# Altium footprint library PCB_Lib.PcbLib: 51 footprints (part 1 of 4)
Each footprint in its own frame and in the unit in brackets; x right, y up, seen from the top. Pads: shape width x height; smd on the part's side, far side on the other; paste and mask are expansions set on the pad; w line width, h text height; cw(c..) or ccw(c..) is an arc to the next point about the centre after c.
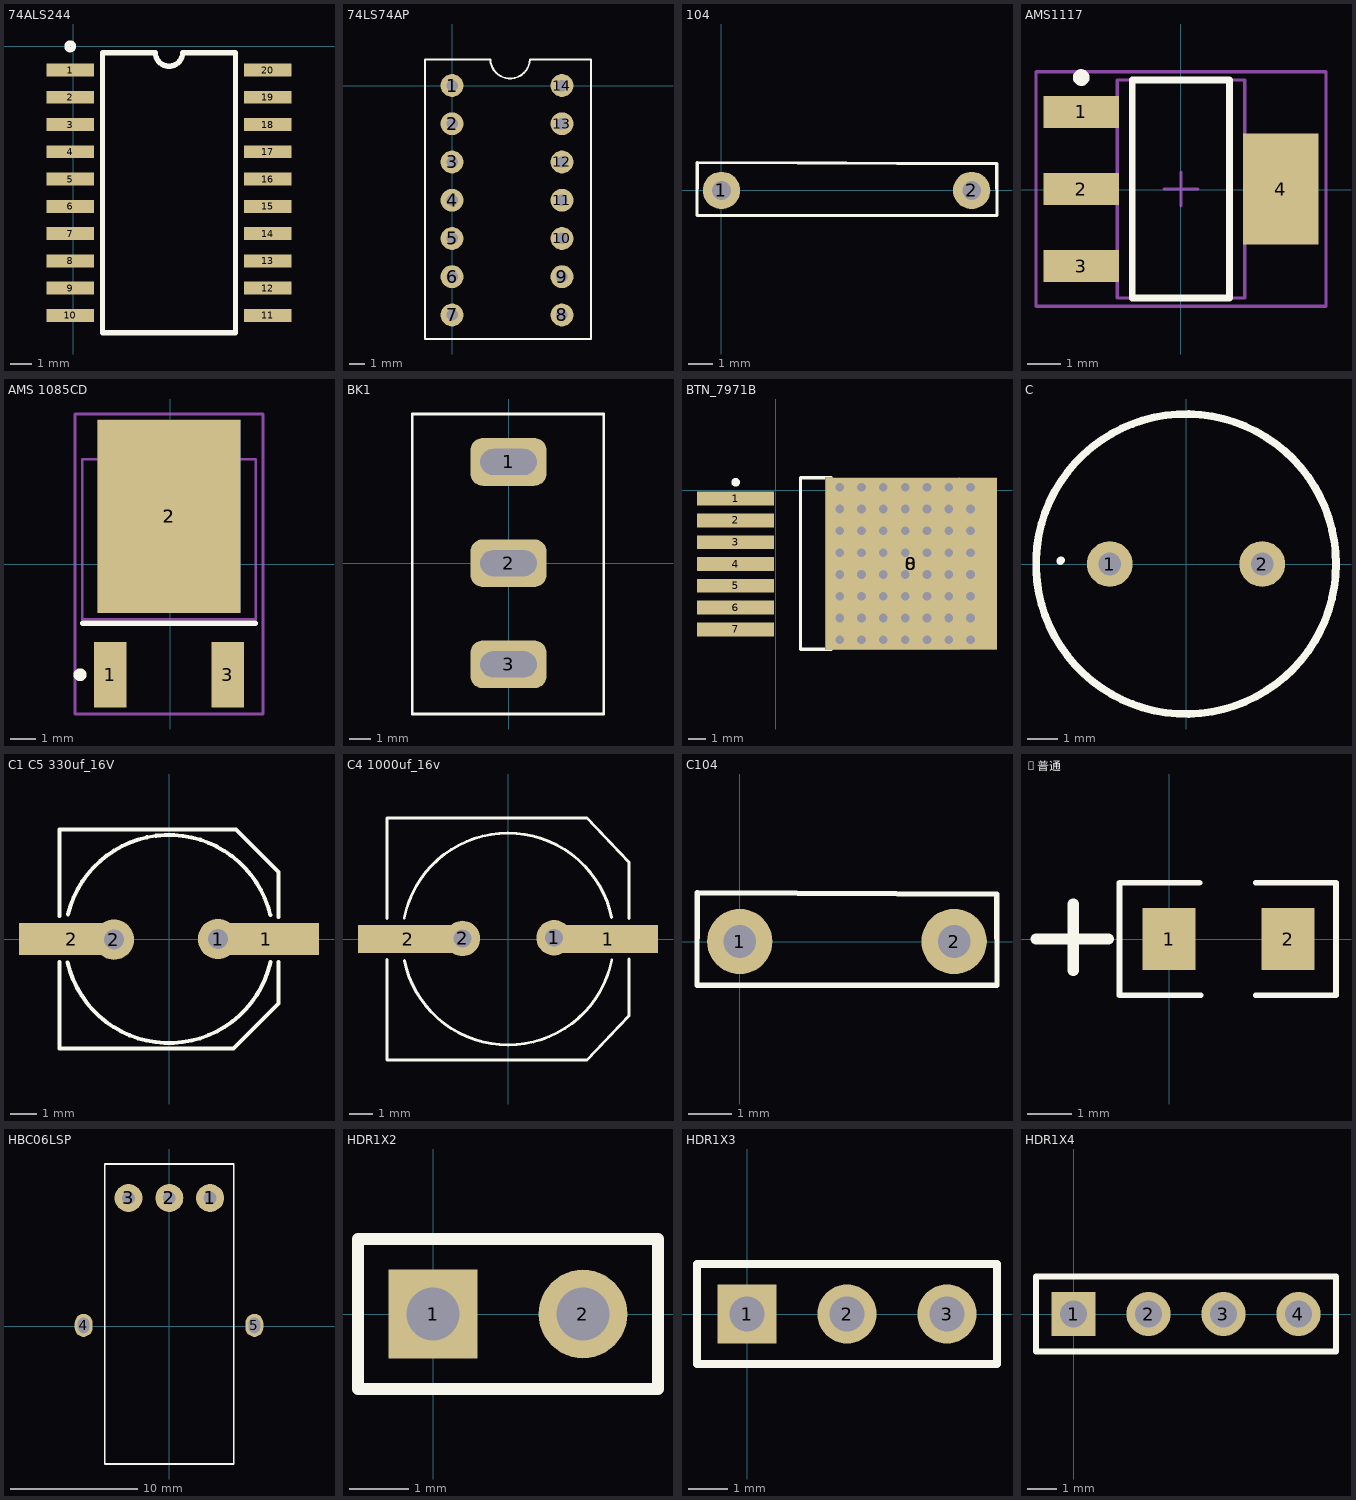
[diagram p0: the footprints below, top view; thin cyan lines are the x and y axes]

## 74ALS244 [mm]
pads (20):
  rect 2.2x0.6 smd: 1(-0.15,-1.1) 2(-0.15,-2.37) 3(-0.15,-3.64) 4(-0.15,-4.91) 5(-0.15,-6.18) 6(-0.15,-7.45) 7(-0.15,-8.72) 8(-0.15,-9.99) 9(-0.15,-11.26) 10(-0.15,-12.53) 11(9.05,-12.53) 12(9.05,-11.26) 13(9.05,-9.99) 14(9.05,-8.72) 15(9.05,-7.45) 16(9.05,-6.18) 17(9.05,-4.91) 18(9.05,-3.64) 19(9.05,-2.37) 20(9.05,-1.1)
Top Overlay:
  circle w0.25: c-0.15,0 r0.15
  lines w0.25: 1.35,-13.34 1.35,-0.29 3.815,-0.29 ccw(c4.45,-0.29) 5.085,-0.29 7.55,-0.29 7.55,-13.34 1.35,-13.34

## 74LS74AP [mil]
pads (14):
  round 60 hole 30 square: 1(0,0)
  round 60 hole 30: 2(0,-100) 3(0,-200) 4(0,-300) 5(0,-400) 6(0,-500) 7(0,-600) 8(287.4,-600) 9(287.4,-500) 10(287.4,-400) 11(287.4,-300) 12(287.4,-200) 13(287.4,-100) 14(287.4,0)
Top Overlay:
  lines w5: 100,68 -71,68 -71,-663 235,-663 363.63,-663 363.63,68 203.48,68 ; 100.04,68 ccw(c151.74,70) 203.44,68

## 104 [mil]
pads (2):
  round 60 hole 30: 1(0,0) 2(401.57,0)
Top Overlay:
  lines w5: -39.29,-40 442.2,-40 441.85,42.84 -38.91,44.65 -39.29,-40

## AMS1117 [mm]
height 1.65
pads (4):
  rect 2.25x0.95 smd: 1(-2.975,2.325) 2(-2.975,0.025) 3(-2.975,-2.275)
  rect 2.25x3.3 smd: 4(2.975,0.025)
Top Overlay:
  circle w0.25: c-2.975,3.35 r0.125
  lines w0.2: -1.45,-3.225 -1.45,3.275 1.45,3.275 1.45,-3.225 -1.45,-3.225
Mechanical 13:
  lines w0.1: -1.9,-3.225 -1.9,3.275 1.9,3.275 1.9,-3.225 -1.9,-3.225
Mechanical 15:
  lines w0.1: -0.5,0.025 0.5,0.025 ; 0,-0.475 0,0.525 ; -4.325,-3.475 -4.325,3.525 4.325,3.525 4.325,-3.475 -4.325,-3.475
3D body: height 1.65, standoff 0.1, extent -1.9,-3.225 1.9,3.275

## AMS 1085CD [mm]
pads (4):
  rect 1.25x2.55 smd: 1(-2.331,-4.3) 3(2.229,-4.3)
  rect 5.55x7.5 smd: 2(-0.051,1.85)
  rect 5.55x7.5 smd far side: 2(-0.051,1.854)
Top Overlay:
  circle w0.25: c-3.506,-4.3 r0.125
  lines w0.2: -3.401,-2.3 3.299,-2.3
Mechanical 13:
  lines w0.1: -3.426,-2.15 -3.426,4.07 3.324,4.07 3.324,-2.15 -3.426,-2.15
Mechanical 15:
  lines w0.1: -0.551,0 0.449,0 ; -0.051,-0.5 -0.051,0.5 ; -3.701,-5.825 -3.701,5.825 3.599,5.825 3.599,-5.825 -3.701,-5.825
3D body: height 2.38, standoff 0.46, extent -3.426,-2.15 3.324,4.07

## BK1 [mm]
pads (3):
  rrect50% 3.5x2.2 hole 1.2 slot 2.6 at 0 deg: 1(0,4.67) 2(0,0) 3(0,-4.67)
Top Overlay:
  lines w0.127: -4.445,-6.96 -4.445,6.883 4.394,6.883 4.394,5.661 4.394,-6.96 -4.445,-6.96

## BTN_7971B [mm]
height 4.4
pads (9):
  rect 10x10 smd far side: 0(7.896,-4.267)
  rect 4.5x0.8 smd: 1(-2.334,-0.483) 2(-2.334,-1.753) 3(-2.334,-3.023) 4(-2.334,-4.293) 5(-2.334,-5.563) 6(-2.334,-6.833) 7(-2.334,-8.103)
  rect 10x10 smd: 8(7.896,-4.267)
via 8.814,-4.902 diameter 0.762 hole 0.508
via 11.354,-1.092 diameter 0.762 hole 0.508
via 11.354,-2.362 diameter 0.762 hole 0.508
via 11.354,-3.632 diameter 0.762 hole 0.508
via 11.354,-4.902 diameter 0.762 hole 0.508
via 10.084,-1.092 diameter 0.762 hole 0.508
via 10.084,-2.362 diameter 0.762 hole 0.508
via 10.084,-3.632 diameter 0.762 hole 0.508
via 10.084,-4.902 diameter 0.762 hole 0.508
via 8.814,-1.092 diameter 0.762 hole 0.508
via 8.814,-2.362 diameter 0.762 hole 0.508
via 8.814,-3.632 diameter 0.762 hole 0.508
via 7.544,-1.092 diameter 0.762 hole 0.508
via 7.544,-2.362 diameter 0.762 hole 0.508
via 7.544,-3.632 diameter 0.762 hole 0.508
via 7.544,-4.902 diameter 0.762 hole 0.508
via 6.274,-1.092 diameter 0.762 hole 0.508
via 6.274,-2.362 diameter 0.762 hole 0.508
via 6.274,-3.632 diameter 0.762 hole 0.508
via 6.274,-4.902 diameter 0.762 hole 0.508
via 5.004,-1.092 diameter 0.762 hole 0.508
via 5.004,-2.362 diameter 0.762 hole 0.508
via 5.004,-3.632 diameter 0.762 hole 0.508
via 5.004,-4.902 diameter 0.762 hole 0.508
via 11.354,-6.172 diameter 0.762 hole 0.508
via 11.354,-7.442 diameter 0.762 hole 0.508
via 11.354,-8.712 diameter 0.762 hole 0.508
via 10.084,-6.172 diameter 0.762 hole 0.508
via 10.084,-7.442 diameter 0.762 hole 0.508
via 10.084,-8.712 diameter 0.762 hole 0.508
via 8.814,-6.172 diameter 0.762 hole 0.508
via 8.814,-7.442 diameter 0.762 hole 0.508
via 8.814,-8.712 diameter 0.762 hole 0.508
via 7.544,-6.172 diameter 0.762 hole 0.508
via 7.544,-7.442 diameter 0.762 hole 0.508
via 7.544,-8.712 diameter 0.762 hole 0.508
via 6.274,-6.172 diameter 0.762 hole 0.508
via 6.274,-7.442 diameter 0.762 hole 0.508
via 6.274,-8.712 diameter 0.762 hole 0.508
via 5.004,-6.172 diameter 0.762 hole 0.508
via 5.004,-7.442 diameter 0.762 hole 0.508
via 5.004,-8.712 diameter 0.762 hole 0.508
via 11.354,0.178 diameter 0.762 hole 0.508
via 10.084,0.178 diameter 0.762 hole 0.508
via 8.814,0.178 diameter 0.762 hole 0.508
via 7.544,0.178 diameter 0.762 hole 0.508
via 6.274,0.178 diameter 0.762 hole 0.508
via 5.004,0.178 diameter 0.762 hole 0.508
via 3.734,-8.712 diameter 0.762 hole 0.508
via 3.734,-7.442 diameter 0.762 hole 0.508
via 3.734,-4.902 diameter 0.762 hole 0.508
via 3.734,-6.172 diameter 0.762 hole 0.508
via 3.734,-3.632 diameter 0.762 hole 0.508
via 3.734,-2.362 diameter 0.762 hole 0.508
via 3.734,-1.092 diameter 0.762 hole 0.508
via 3.734,0.178 diameter 0.762 hole 0.508
Top Overlay:
  circle w0.25: c-2.334,0.467 r0.125
  lines w0.2: 3.246,-9.267 1.446,-9.267 1.446,0.733 3.246,0.733
Mechanical 13:
  lines w0.1: 1.446,0.733 1.446,-9.267 10.696,-9.267 10.696,0.733
Mechanical 15:
  lines w0.1: 3.596,-4.267 4.596,-4.267 ; 4.096,-4.767 4.096,-3.767
3D body: height 4.4, standoff 0.5, extent 1.446,-9.267 10.696,0.733

## C [mil]
pads (2):
  round 60 hole 30: 1(-100,0) 2(100,0)
Top Overlay:
  circle w10: c0,0 r196.85
  lines w10: -165,4 -164,5

## C1 C5 330uf_16V [mil]
pads (4):
  round 60 hole 30: 1(73,0) 2(-82,-1)
  rect 157.48x47.24 smd: 1(144.69,0) 2(-144.69,0)
Top Overlay:
  lines w6: -163.39,-34 -163.39,-163.39 96,-163.39 163.39,-96 163.39,-34 ; -163.39,34 -163.39,163.39 99.61,163.39 163.39,99.61 163.39,33 ; -151.06,-34.7 ccw(c0,0) 151.12,-34.48 ; -150.55,36.87 cw(c0,0) 150.84,35.67

## C4 1000uf_16v [mil]
pads (4):
  round 60 hole 30: 1(78,2) 2(-77,1)
  rect 169.29x47.24 smd: 1(169.29,0) 2(-169.29,0)
Top Overlay:
  lines w5: -204.72,-35 -204.72,-204.72 133.86,-204.72 204.72,-129.92 204.72,-34 ; -204.72,35 -204.72,204.72 133.86,204.72 204.72,129.92 204.72,35 ; -175.68,35.75 cw(c0,0) 175.52,36.52 ; -175.52,-36.52 ccw(c0,0) 175.68,-35.75

## C104 [mil]
pads (2):
  round 60 hole 30: 1(0,0) 2(196.85,0)
Top Overlay:
  lines w5: -39.29,-40 236.22,-40 235.86,43.62 -38.91,44.65 -39.29,-40

## C普通 [mm]
pads (2):
  rect 1.2x1.4 smd: 1(0,0) 2(2.68,0)
Top Overlay:
  lines w0.127: 0.686,1.27 -1.118,1.27 -1.118,-1.27 0.711,-1.27 ; 1.956,-1.27 3.734,-1.27 3.759,-1.27 3.759,1.27 1.956,1.27
  lines w0.254: -2.997,0 -1.372,0 ; -2.159,-0.711 -2.159,0.787 -2.159,0

## HBC06LSP [mm]
pads (5):
  round 2.2 hole 1 square: 1(3.226,10.084)
  round 2.2 hole 1: 2(0.026,10.084) 3(-3.174,10.084)
  oval 1.4x1.8 hole 0.9 slot 1.2 at 90 deg: 4(-6.7,0.084) 5(6.7,0.084)
Top Overlay:
  lines w0.127: 5.081,12.725 5.081,-10.793 4.914,-10.793 -5.028,-10.793 -5.028,12.751 5.081,12.751

## HDR1X2 [mm] "Connector; Header; 2 Position"
pads (2):
  rect 1.5x1.5 hole 0.9: 1(0,0)
  round 1.5 hole 0.9: 2(2.54,0)
Top Overlay:
  lines w0.2: -1.27,-1.27 -1.27,1.27 3.81,1.27 3.81,-1.27 -1.27,-1.27

## HDR1X3 [mm] "Connector; Header; 3 Position"
pads (3):
  rect 1.5x1.5 hole 0.9: 1(0,0)
  round 1.5 hole 0.9: 2(2.54,0) 3(5.08,0)
Top Overlay:
  lines w0.2: -1.27,-1.27 -1.27,1.27 6.35,1.27 6.35,-1.27 -1.27,-1.27

## HDR1X4 [mm] "Connector; Header; 4 Position"
pads (4):
  rect 1.5x1.5 hole 0.9: 1(0,0)
  round 1.5 hole 0.9: 2(2.54,0) 3(5.08,0) 4(7.62,0)
Top Overlay:
  lines w0.2: -1.27,-1.27 -1.27,1.27 8.89,1.27 8.89,-1.27 -1.27,-1.27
